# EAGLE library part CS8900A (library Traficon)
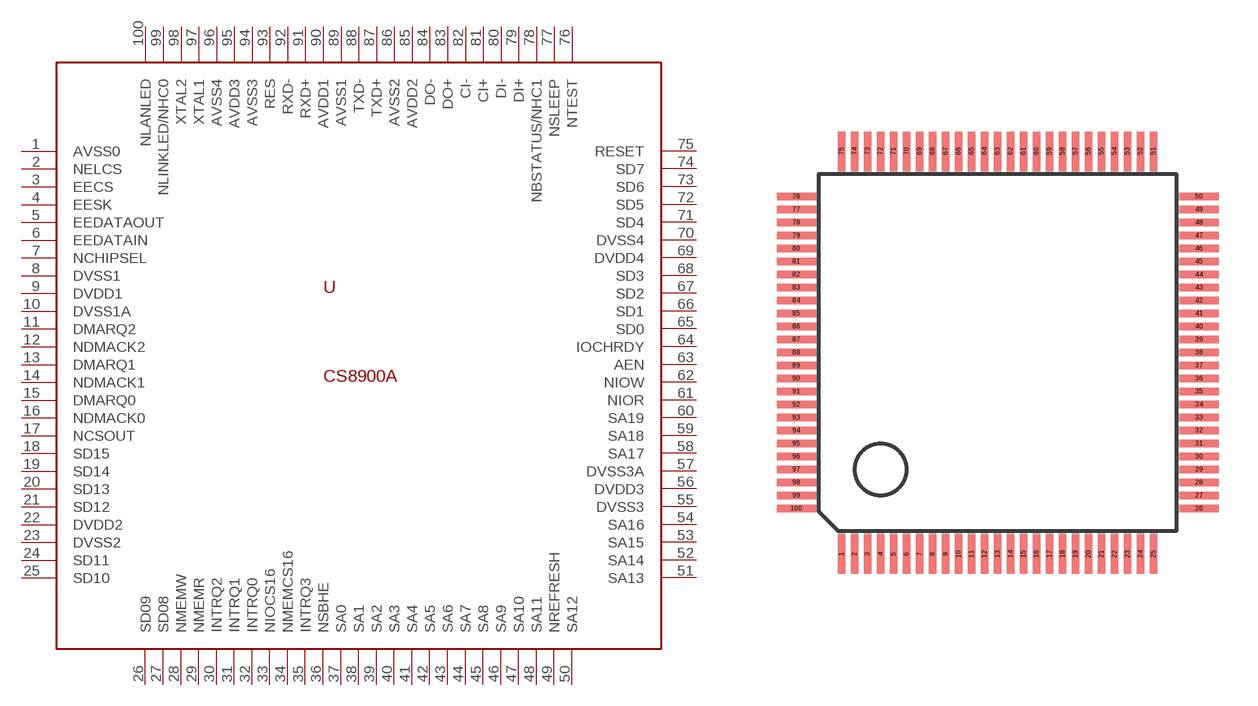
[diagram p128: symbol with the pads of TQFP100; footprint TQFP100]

Designator prefix U

## CS8900A  [TQFP100]
1  AVSS0
2  NELCS
3  EECS
4  EESK
5  EEDATAOUT
6  EEDATAIN
7  NCHIPSEL
8  DVSS1
9  DVDD1
10  DVSS1A
11  DMARQ2
12  NDMACK2
13  DMARQ1
14  NDMACK1
15  DMARQ0
16  NDMACK0
17  NCSOUT
18  SD15
19  SD14
20  SD13
21  SD12
22  DVDD2
23  DVSS2
24  SD11
25  SD10
26  SD09
27  SD08
28  NMEMW
29  NMEMR
30  INTRQ2
31  INTRQ1
32  INTRQ0
33  NIOCS16
34  NMEMCS16
35  INTRQ3
36  NSBHE
37  SA0
38  SA1
39  SA2
40  SA3
41  SA4
42  SA5
43  SA6
44  SA7
45  SA8
46  SA9
47  SA10
48  SA11
49  NREFRESH
50  SA12
51  SA13
52  SA14
53  SA15
54  SA16
55  DVSS3
56  DVDD3
57  DVSS3A
58  SA17
59  SA18
60  SA19
61  NIOR
62  NIOW
63  AEN
64  IOCHRDY
65  SD0
66  SD1
67  SD2
68  SD3
69  DVDD4
70  DVSS4
71  SD4
72  SD5
73  SD6
74  SD7
75  RESET
76  NTEST
77  NSLEEP
78  NBSTATUS/NHC1
79  DI+
80  DI-
81  CI+
82  CI-
83  DO+
84  DO-
85  AVDD2
86  AVSS2
87  TXD+
88  TXD-
89  AVSS1
90  AVDD1
91  RXD+
92  RXD-
93  RES
94  AVSS3
95  AVDD3
96  AVSS4
97  XTAL1
98  XTAL2
99  NLINKLED/NHC0
100  NLANLED

## Footprint TQFP100 (pad centres in mm)
Thin Quad Flat Pack
smd 0.27 x 1.5: 1 -6,-7.75; 2 -5.5,-7.75; 3 -5,-7.75; 4 -4.5,-7.75; 5 -4,-7.75; 6 -3.5,-7.75; 7 -3,-7.75; 8 -2.5,-7.75; 9 -2,-7.75; 10 -1.5,-7.75; 11 -1,-7.75; 12 -0.5,-7.75; 13 0,-7.75; 14 0.5,-7.75; 15 1,-7.75; 16 1.5,-7.75; 17 2,-7.75; 18 2.5,-7.75; 19 3,-7.75; 20 3.5,-7.75; 21 4,-7.75; 22 4.5,-7.75; 23 5,-7.75; 24 5.5,-7.75; 25 6,-7.75; 51 6,7.75; 52 5.5,7.75; 53 5,7.75; 54 4.5,7.75; 55 4,7.75; 56 3.5,7.75; 57 3,7.75; 58 2.5,7.75; 59 2,7.75; 60 1.5,7.75; 61 1,7.75; 62 0.5,7.75; 63 0,7.75; 64 -0.5,7.75; 65 -1,7.75; 66 -1.5,7.75; 67 -2,7.75; 68 -2.5,7.75; 69 -3,7.75; 70 -3.5,7.75; 71 -4,7.75; 72 -4.5,7.75; 73 -5,7.75; 74 -5.5,7.75; 75 -6,7.75
smd 1.5 x 0.27: 26 7.75,-6; 27 7.75,-5.5; 28 7.75,-5; 29 7.75,-4.5; 30 7.75,-4; 31 7.75,-3.5; 32 7.75,-3; 33 7.75,-2.5; 34 7.75,-2; 35 7.75,-1.5; 36 7.75,-1; 37 7.75,-0.5; 38 7.75,0; 39 7.75,0.5; 40 7.75,1; 41 7.75,1.5; 42 7.75,2; 43 7.75,2.5; 44 7.75,3; 45 7.75,3.5; 46 7.75,4; 47 7.75,4.5; 48 7.75,5; 49 7.75,5.5; 50 7.75,6; 76 -7.75,6; 77 -7.75,5.5; 78 -7.75,5; 79 -7.75,4.5; 80 -7.75,4; 81 -7.75,3.5; 82 -7.75,3; 83 -7.75,2.5; 84 -7.75,2; 85 -7.75,1.5; 86 -7.75,1; 87 -7.75,0.5; 88 -7.75,0; 89 -7.75,-0.5; 90 -7.75,-1; 91 -7.75,-1.5; 92 -7.75,-2; 93 -7.75,-2.5; 94 -7.75,-3; 95 -7.75,-3.5; 96 -7.75,-4; 97 -7.75,-4.5; 98 -7.75,-5; 99 -7.75,-5.5; 100 -7.75,-6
